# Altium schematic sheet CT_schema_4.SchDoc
size 483 x 463 mm
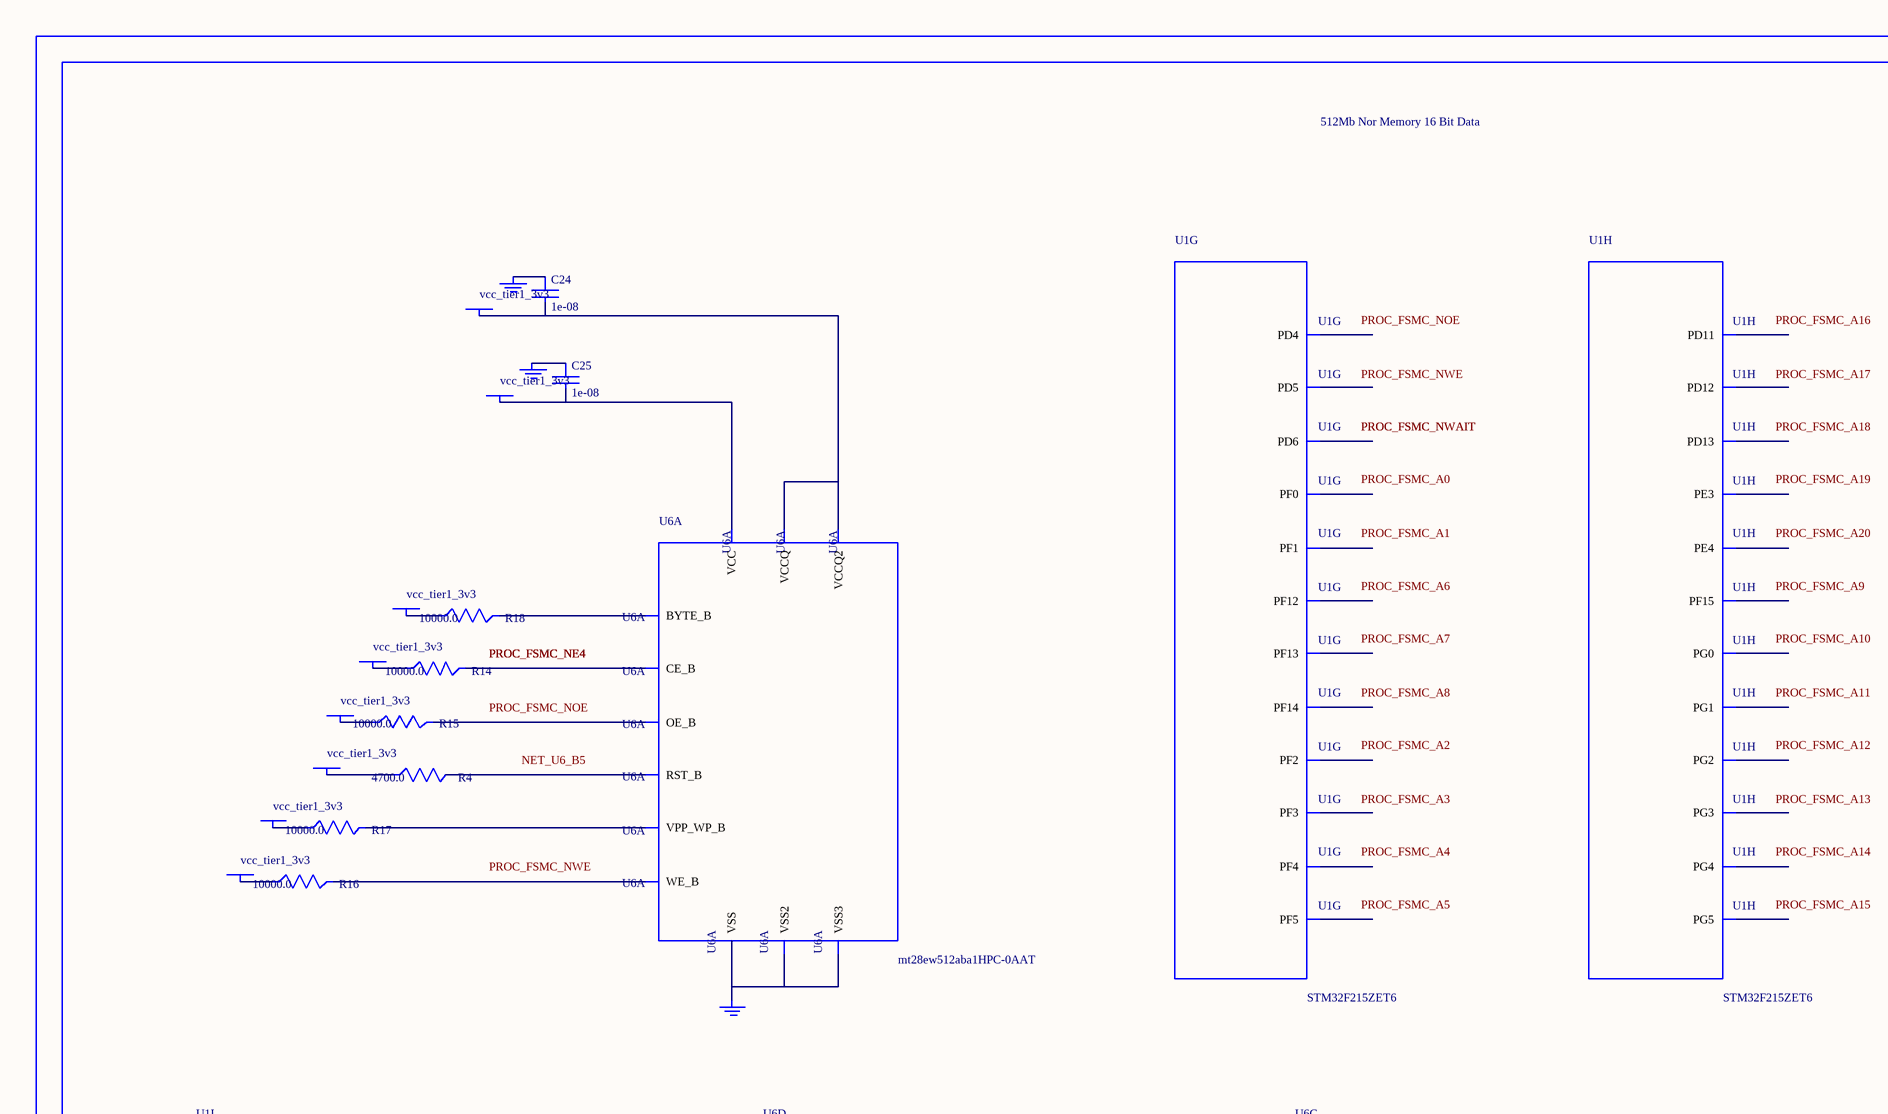
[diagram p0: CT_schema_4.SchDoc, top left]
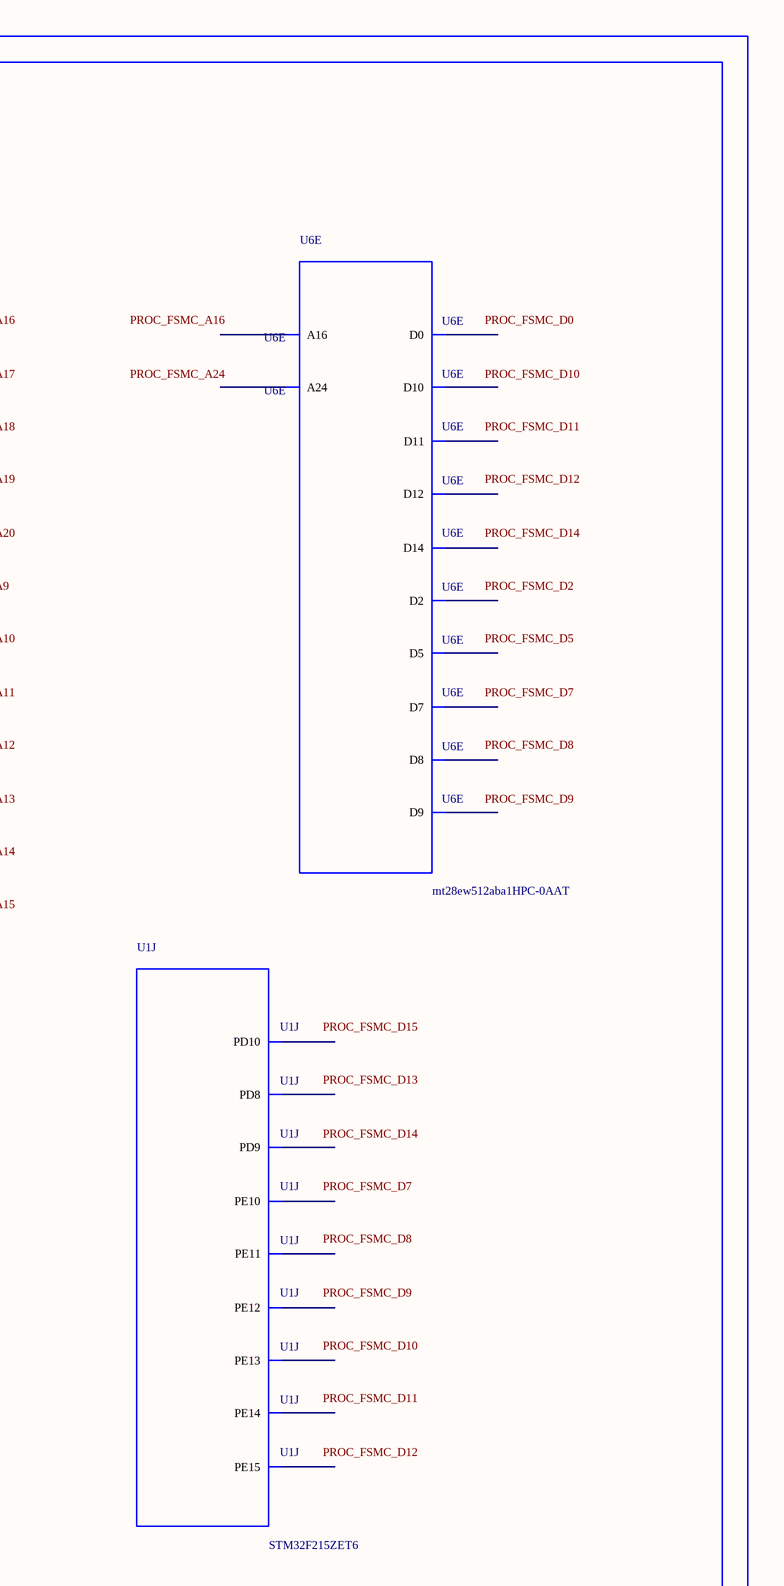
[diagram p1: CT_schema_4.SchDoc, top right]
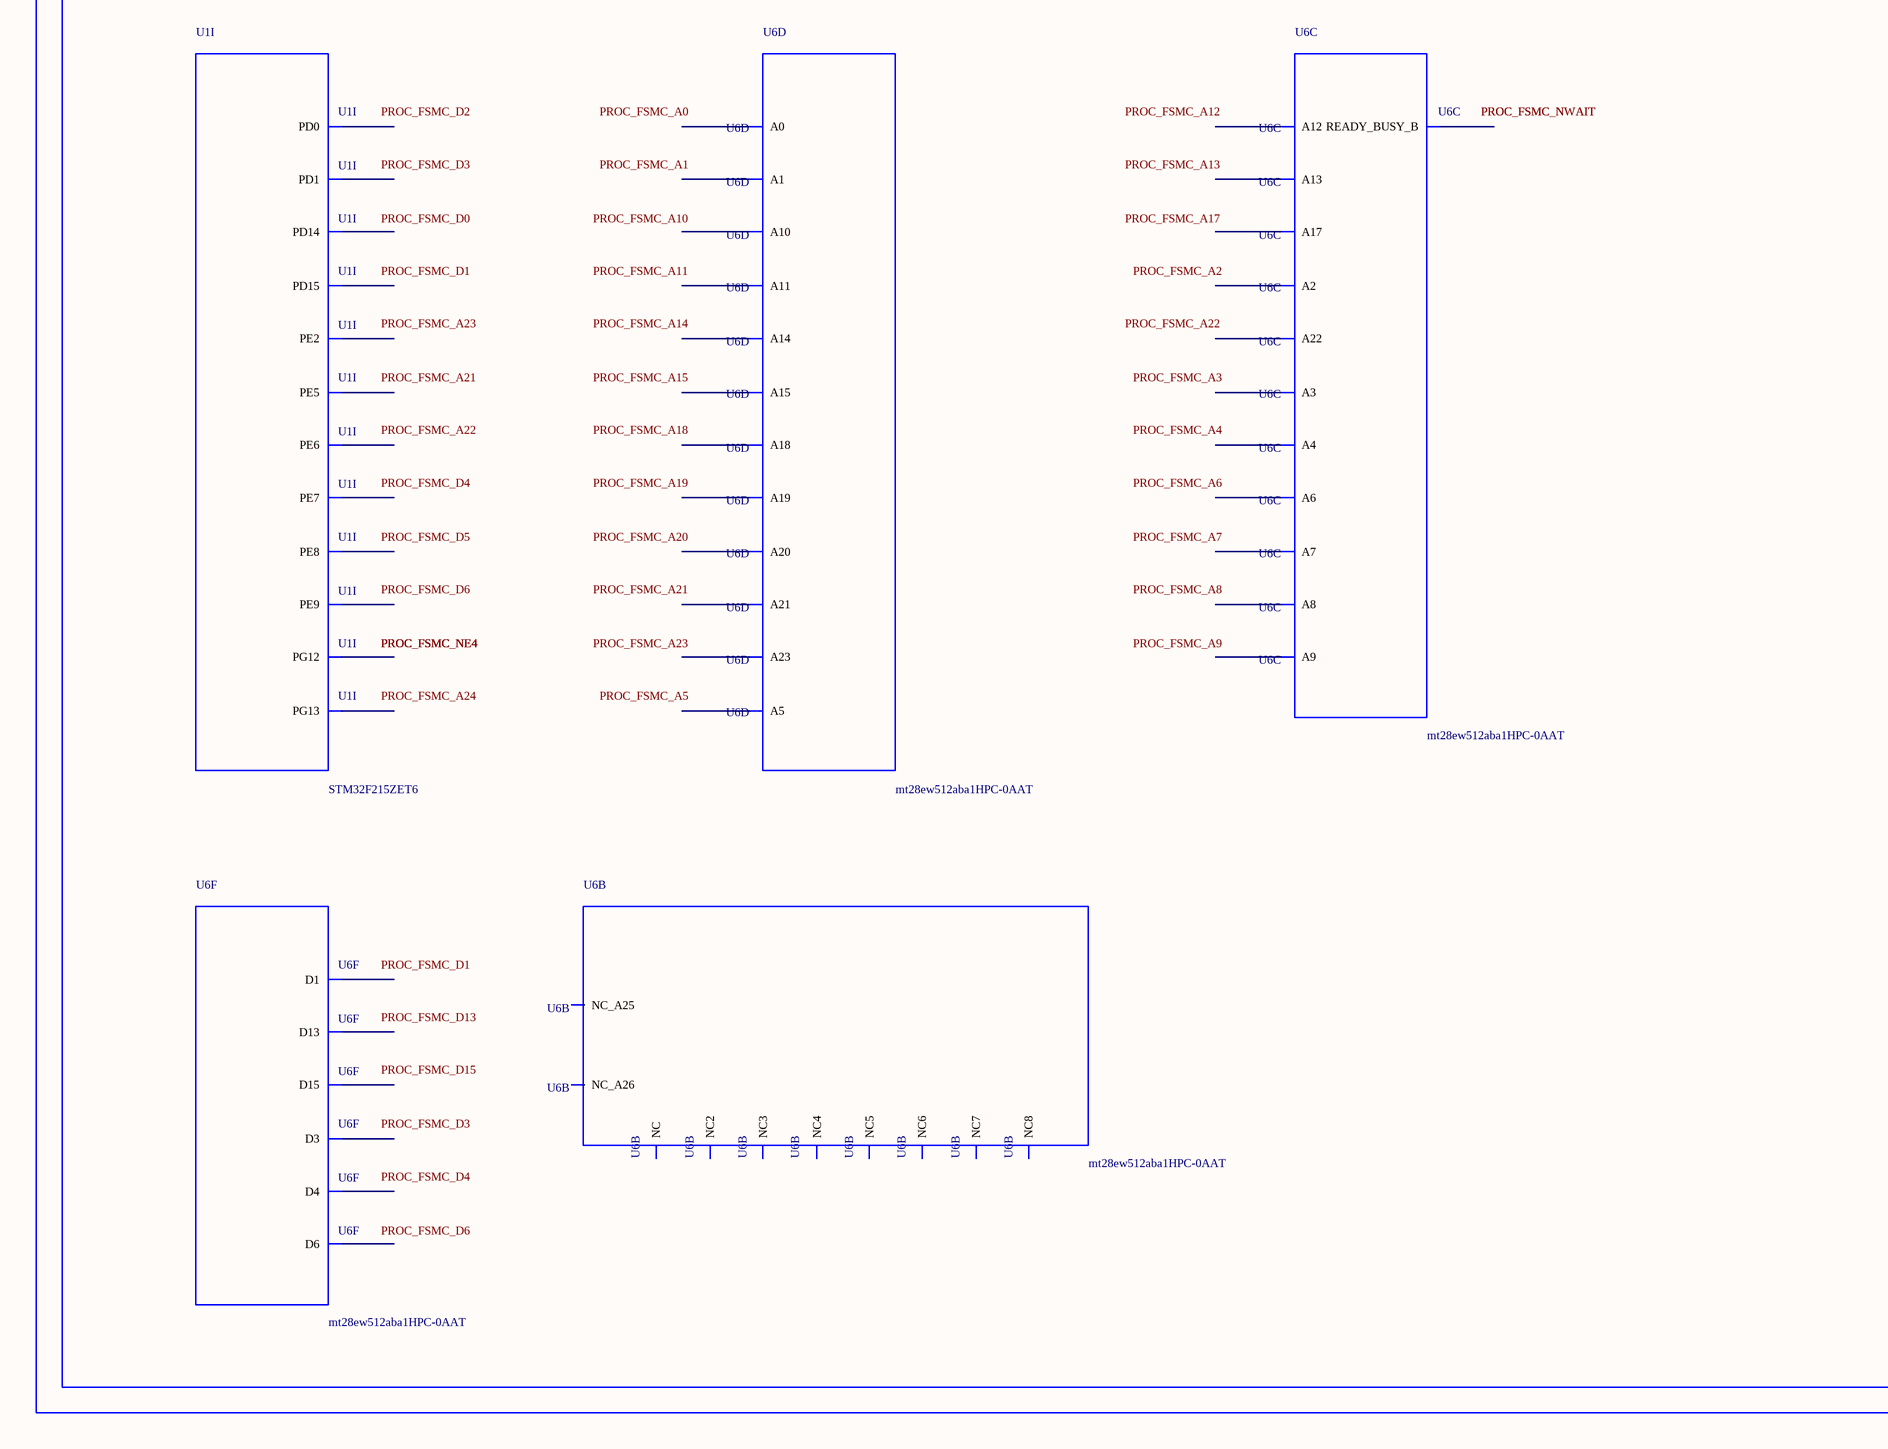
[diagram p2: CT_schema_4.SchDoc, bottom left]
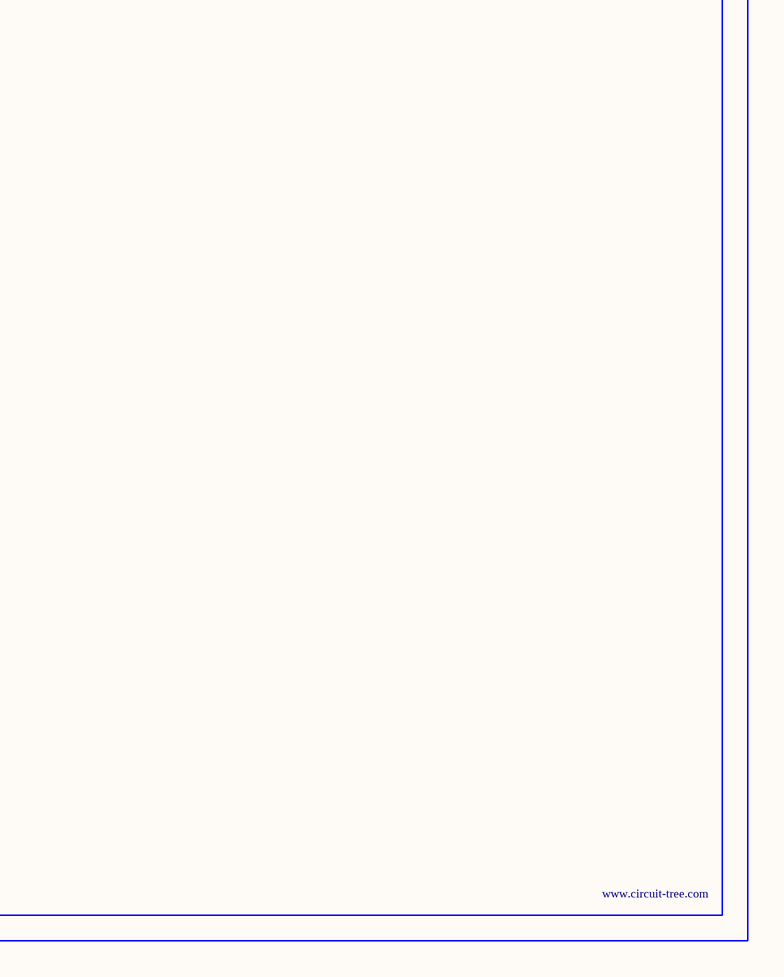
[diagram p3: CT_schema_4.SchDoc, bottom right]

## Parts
BORDER3  (no value)
C24  1e-08  [C0402]
C25  1e-08  [C0402]
GND_INSTANCE_3_0  (no value)
GND_INSTANCE_3_1  (no value)
GND_INSTANCE_3_2  (no value)
POWER_INSTANCE_3_0  vcc_tier1_3v3
POWER_INSTANCE_3_1  vcc_tier1_3v3
POWER_INSTANCE_3_2  vcc_tier1_3v3
POWER_INSTANCE_3_3  vcc_tier1_3v3
POWER_INSTANCE_3_4  vcc_tier1_3v3
POWER_INSTANCE_3_5  vcc_tier1_3v3
POWER_INSTANCE_3_6  vcc_tier1_3v3
POWER_INSTANCE_3_7  vcc_tier1_3v3
R4  4700.0  [R0603]
R14  10000.0  [R0603]
R15  10000.0  [R0603]
R16  10000.0  [R0603]
R17  10000.0  [R0603]
R18  10000.0  [R0603]
U1  STM32F215ZET6  [LQFP144]  (parts G,H,I,J of 12)
U6  mt28ew512aba1HPC-0AAT  [LBGA-64]  (parts A,B,C,D,E,F of 6)

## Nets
NetC24_1: C24.1 GND_INSTANCE_3_0.0(GND)
NetC24_2: C24.2 POWER_INSTANCE_3_0.0(PWR) U6.D8(VCCQ) U6.F1(VCCQ2)
NetC25_1: C25.1 GND_INSTANCE_3_1.0(GND)
NetC25_2: C25.2 POWER_INSTANCE_3_1.0(PWR) U6.G5(VCC)
NetGND_INSTANCE_3_2_0: GND_INSTANCE_3_2.0(GND) U6.E8(VSS) U6.H2(VSS2) U6.H7(VSS3)
NetPOWER_INSTANCE_3_2_0: POWER_INSTANCE_3_2.0(PWR) R14.1
NetPOWER_INSTANCE_3_3_0: POWER_INSTANCE_3_3.0(PWR) R15.1
NetPOWER_INSTANCE_3_4_0: POWER_INSTANCE_3_4.0(PWR) R16.1
NetPOWER_INSTANCE_3_5_0: POWER_INSTANCE_3_5.0(PWR) R17.1
NetPOWER_INSTANCE_3_6_0: POWER_INSTANCE_3_6.0(PWR) R18.1
NetPOWER_INSTANCE_3_7_0: POWER_INSTANCE_3_7.0(PWR) R4.1
NetR4_2: R4.2 U6.B5(RST_B)
NetR14_2: R14.2 U6.F2(CE_B)
NetR15_2: R15.2 U6.G2(OE_B)
NetR16_2: R16.2 U6.A5(WE_B)
NetR17_2: R17.2 U6.B4(VPP_WP_B)
NetR18_2: R18.2 U6.F7(BYTE_B)

Not connected (* = marked no-connect by the designer): U1 1(PE2) 2(PE3) 3(PE4) 4(PE5) 5(PE6) 10(PF0) 11(PF1) 12(PF2) 13(PF3) 14(PF4) 15(PF5) 50(PF12) 53(PF13) 54(PF14) 55(PF15) 56(PG0) 57(PG1) 58(PE7) 59(PE8) 60(PE9) 63(PE10) 64(PE11) 65(PE12) 66(PE13) 67(PE14) 68(PE15) 77(PD8) 78(PD9) 79(PD10) 80(PD11) 81(PD12) 82(PD13) 85(PD14) 86(PD15) 87(PG2) 88(PG3) 89(PG4) 90(PG5) 114(PD0) 115(PD1) 118(PD4) 119(PD5) 122(PD6) 127(PG12) 128(PG13); U6 A1(NC) A2(A3) A3(A7) A4(READY_BUSY_B) A6(A9) A7(A13) A8(NC2) B1(NC_A26) B2(A4) B3(A17) B6(A8) B7(A12) B8(A22) C1(NC3) C2(A2) C3(A6) C4(A18) C5(A21) C6(A10) C7(A14) C8(A23) D1(NC4) D2(A1) D3(A5) D4(A20) D5(A19) D6(A11) D7(A15) E1(NC5) E2(A0) E3(D0) E4(D2) E5(D5) E6(D7) E7(A16) F3(D8) F4(D10) F5(D12) F6(D14) F8(A24) G1(NC6) G3(D9) G4(D11) G6(D13) G7(D15) G8(NC_A25) H1(NC7) H3(D1) H4(D3) H5(D4) H6(D6) H8(NC8)

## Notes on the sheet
- Labels drawn without touching a wire or pin: NET_U6_B5, PROC_FSMC_A0, PROC_FSMC_A1, PROC_FSMC_A2, PROC_FSMC_A3, PROC_FSMC_A4, PROC_FSMC_A5, PROC_FSMC_A6, PROC_FSMC_A7, PROC_FSMC_A8, PROC_FSMC_A9, PROC_FSMC_A10, PROC_FSMC_A11, PROC_FSMC_A12, PROC_FSMC_A13, PROC_FSMC_A14, PROC_FSMC_A15, PROC_FSMC_A16, PROC_FSMC_A17, PROC_FSMC_A18, PROC_FSMC_A19, PROC_FSMC_A20, PROC_FSMC_A21, PROC_FSMC_A22, PROC_FSMC_A23, PROC_FSMC_A24, PROC_FSMC_D0, PROC_FSMC_D1, PROC_FSMC_D2, PROC_FSMC_D3, PROC_FSMC_D4, PROC_FSMC_D5, PROC_FSMC_D6, PROC_FSMC_D7, PROC_FSMC_D8, PROC_FSMC_D9, PROC_FSMC_D10, PROC_FSMC_D11, PROC_FSMC_D12, PROC_FSMC_D13, PROC_FSMC_D14, PROC_FSMC_D15, PROC_FSMC_NOE, PROC_FSMC_NWE

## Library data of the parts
BORDER3 = BORDER_PAGE3
C24 C25 = C0402C103K3RAC
GND_INSTANCE_3_0-GND_INSTANCE_3_2 = GND
POWER_INSTANCE_3_0-POWER_INSTANCE_3_7 = PWR
R4 = RC0603JR-074K7L
R14-R18 = RC0603JR-0710KL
